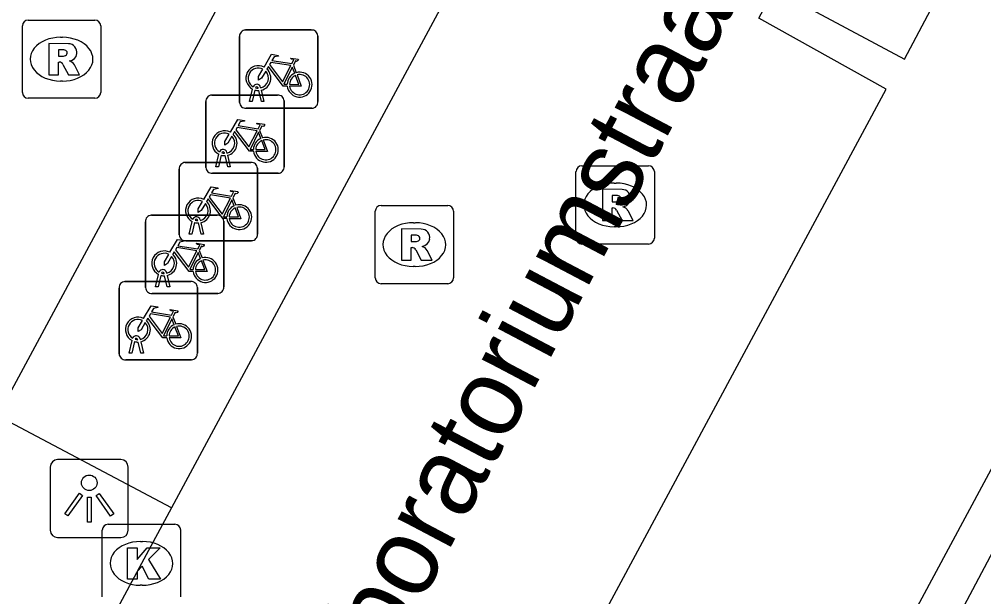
# Model space of a CAD drawing. Extents: x 159489 to 160304, y 383826 to 384530.
# Drawn here: x 159629.86 to 159642.18, y 384196.3 to 384203.68 of the extents above; entities that cross this region are included whole.
import ezdxf

# ---------------------------------------------------------------- set-up
doc = ezdxf.new("R2010")
doc.units = 0
for name, color, linetype in [('IMGEO_Fietsenrek', 7, 'Continuous'), ('IMGEO_Kolk', 7, 'Continuous'), ('IMGEO_Lichtpunt', 7, 'Continuous'), ('IMGEO_Openbare_ruimte_label', 7, 'Continuous'), ('IMGEO_Parkeervlak_open', 7, 'Continuous'), ('IMGEO_Rijbaan_lokaal_gesloten', 7, 'Continuous'), ('IMGEO_Rioolput', 7, 'Continuous'), ('IMGEO_Voetpad_gesloten', 7, 'Continuous'), ('IMGEO_Voetpad_open', 7, 'Continuous')]:
    doc.layers.add(name, color=color, linetype=linetype)

msp = doc.modelspace()

# ---------------------------------------------------------------- linework, layer by layer
at = {"layer": 'IMGEO_Fietsenrek'}
for p, q in [((159632.75, 384203.544), (159633.591, 384203.544)), ((159633.591, 384203.544), (159632.75, 384203.544)), ((159632.675, 384202.619), (159632.675, 384203.46)), ((159632.675, 384203.46), (159632.675, 384202.619)), ((159633.675, 384203.469), (159633.675, 384202.628)), ((159633.675, 384202.628), (159633.675, 384203.469)), ((159633.362, 384203.093), (159633.398, 384202.998)), ((159632.802, 384202.628), (159632.841, 384202.788)), ((159632.871, 384202.776), (159632.836, 384202.628)), ((159632.913, 384202.8), (159632.912, 384202.804)), ((159632.954, 384202.628), (159632.92, 384202.77)), ((159632.944, 384202.811), (159632.945, 384202.804)), ((159632.952, 384202.774), (159632.987, 384202.628)), ((159632.319, 384202.712), (159633.16, 384202.712)), ((159633.16, 384202.712), (159632.319, 384202.712)), ((159632.244, 384201.787), (159632.244, 384202.628)), ((159632.244, 384202.628), (159632.244, 384201.787)), ((159633.6, 384202.544), (159632.759, 384202.544)), ((159632.759, 384202.544), (159633.6, 384202.544)), ((159632.836, 384202.628), (159632.802, 384202.628)), ((159632.987, 384202.628), (159632.954, 384202.628)), ((159633.244, 384202.637), (159633.244, 384201.796)), ((159633.244, 384201.796), (159633.244, 384202.637)), ((159632.931, 384202.261), (159632.967, 384202.166)), ((159632.371, 384201.796), (159632.41, 384201.956)), ((159632.44, 384201.944), (159632.405, 384201.796)), ((159632.482, 384201.968), (159632.481, 384201.972)), ((159632.523, 384201.796), (159632.489, 384201.938)), ((159632.513, 384201.979), (159632.514, 384201.972)), ((159632.521, 384201.942), (159632.556, 384201.796)), ((159631.979, 384201.851), (159632.82, 384201.851)), ((159632.82, 384201.851), (159631.979, 384201.851)), ((159632.405, 384201.796), (159632.371, 384201.796)), ((159632.556, 384201.796), (159632.523, 384201.796)), ((159632.904, 384201.776), (159632.904, 384200.935)), ((159632.904, 384200.935), (159632.904, 384201.776)), ((159631.904, 384200.926), (159631.904, 384201.767)), ((159631.904, 384201.767), (159631.904, 384200.926)), ((159633.169, 384201.712), (159632.328, 384201.712)), ((159632.328, 384201.712), (159633.169, 384201.712)), ((159632.591, 384201.4), (159632.627, 384201.305)), ((159631.548, 384201.176), (159632.389, 384201.176)), ((159632.389, 384201.176), (159631.548, 384201.176)), ((159631.473, 384200.251), (159631.473, 384201.092)), ((159631.473, 384201.092), (159631.473, 384200.251)), ((159632.031, 384200.935), (159632.07, 384201.095)), ((159632.1, 384201.083), (159632.065, 384200.935)), ((159632.142, 384201.107), (159632.141, 384201.111)), ((159632.183, 384200.935), (159632.149, 384201.077)), ((159632.173, 384201.118), (159632.174, 384201.111)), ((159632.181, 384201.081), (159632.216, 384200.935)), ((159632.473, 384201.101), (159632.473, 384200.26)), ((159632.473, 384200.26), (159632.473, 384201.101)), ((159632.065, 384200.935), (159632.031, 384200.935)), ((159632.216, 384200.935), (159632.183, 384200.935)), ((159632.829, 384200.851), (159631.988, 384200.851)), ((159631.988, 384200.851), (159632.829, 384200.851)), ((159632.16, 384200.725), (159632.196, 384200.63)), ((159631.6, 384200.26), (159631.639, 384200.42)), ((159631.711, 384200.432), (159631.71, 384200.436)), ((159631.742, 384200.443), (159631.743, 384200.436)), ((159631.211, 384200.329), (159632.052, 384200.329)), ((159632.052, 384200.329), (159631.211, 384200.329)), ((159631.669, 384200.408), (159631.634, 384200.26)), ((159631.752, 384200.26), (159631.718, 384200.402)), ((159631.75, 384200.406), (159631.785, 384200.26)), ((159631.136, 384199.404), (159631.136, 384200.245)), ((159631.136, 384200.245), (159631.136, 384199.404)), ((159632.398, 384200.176), (159631.557, 384200.176)), ((159631.557, 384200.176), (159632.398, 384200.176)), ((159631.634, 384200.26), (159631.6, 384200.26)), ((159631.785, 384200.26), (159631.752, 384200.26)), ((159632.136, 384200.254), (159632.136, 384199.413)), ((159632.136, 384199.413), (159632.136, 384200.254)), ((159631.823, 384199.878), (159631.859, 384199.783)), ((159631.263, 384199.413), (159631.302, 384199.573)), ((159631.332, 384199.561), (159631.297, 384199.413)), ((159631.374, 384199.585), (159631.373, 384199.589)), ((159631.405, 384199.596), (159631.406, 384199.589)), ((159631.413, 384199.559), (159631.448, 384199.413)), ((159631.415, 384199.413), (159631.381, 384199.555)), ((159632.061, 384199.329), (159631.22, 384199.329)), ((159631.22, 384199.329), (159632.061, 384199.329)), ((159631.297, 384199.413), (159631.263, 384199.413)), ((159631.448, 384199.413), (159631.415, 384199.413))]:
    msp.add_line(p, q, dxfattribs=at)
for points in [[(159632.988, 384203.07), (159633.083, 384203.234), (159633.169, 384203.22), (159633.171, 384203.211), (159633.115, 384203.2), (159633.088, 384203.155), (159633.344, 384203.114)], [(159633.344, 384203.114), (159633.369, 384203.163), (159633.363, 384203.167), (159633.34, 384203.171), (159633.328, 384203.178), (159633.327, 384203.181), (159633.329, 384203.186), (159633.424, 384203.171), (159633.426, 384203.161), (159633.416, 384203.148), (159633.404, 384203.142), (159633.39, 384203.148), (159633.362, 384203.093)], [(159633.009, 384203.018), (159632.957, 384202.928), (159632.917, 384202.903), (159632.918, 384202.95), (159632.973, 384203.044)], [(159633.284, 384202.826), (159633.234, 384202.826), (159633.043, 384203.077), (159633.024, 384203.045)], [(159633.331, 384203.089), (159633.074, 384203.13), (159633.057, 384203.101), (159633.224, 384202.881), (159633.331, 384203.089)], [(159633.379, 384202.991), (159633.349, 384203.068), (159633.24, 384202.85), (159633.283, 384202.85)], [(159633.313, 384202.85), (159633.433, 384202.849), (159633.389, 384202.963)], [(159633.409, 384202.97), (159633.464, 384202.825), (159633.314, 384202.825)], [(159632.557, 384202.238), (159632.652, 384202.402), (159632.738, 384202.388), (159632.74, 384202.379), (159632.684, 384202.368), (159632.657, 384202.323), (159632.913, 384202.282)], [(159632.9, 384202.257), (159632.643, 384202.298), (159632.626, 384202.269), (159632.793, 384202.049), (159632.9, 384202.257)], [(159632.913, 384202.282), (159632.938, 384202.331), (159632.932, 384202.335), (159632.909, 384202.339), (159632.897, 384202.346), (159632.896, 384202.349), (159632.898, 384202.354), (159632.993, 384202.339), (159632.995, 384202.329), (159632.985, 384202.316), (159632.973, 384202.31), (159632.959, 384202.316), (159632.931, 384202.261)], [(159632.578, 384202.186), (159632.526, 384202.096), (159632.486, 384202.071), (159632.487, 384202.118), (159632.542, 384202.212)], [(159632.853, 384201.994), (159632.803, 384201.994), (159632.612, 384202.245), (159632.593, 384202.213)], [(159632.948, 384202.159), (159632.918, 384202.236), (159632.809, 384202.018), (159632.852, 384202.018)], [(159632.882, 384202.018), (159633.002, 384202.017), (159632.958, 384202.131)], [(159632.978, 384202.138), (159633.033, 384201.993), (159632.883, 384201.993)], [(159632.217, 384201.377), (159632.312, 384201.541), (159632.398, 384201.527), (159632.4, 384201.518), (159632.344, 384201.507), (159632.317, 384201.462), (159632.573, 384201.421)], [(159632.56, 384201.396), (159632.303, 384201.437), (159632.286, 384201.408), (159632.453, 384201.188), (159632.56, 384201.396)], [(159632.573, 384201.421), (159632.598, 384201.47), (159632.592, 384201.474), (159632.569, 384201.478), (159632.557, 384201.485), (159632.556, 384201.488), (159632.558, 384201.493), (159632.653, 384201.478), (159632.655, 384201.468), (159632.645, 384201.455), (159632.633, 384201.449), (159632.619, 384201.455), (159632.591, 384201.4)], [(159632.238, 384201.325), (159632.186, 384201.235), (159632.146, 384201.21), (159632.147, 384201.257), (159632.202, 384201.351)], [(159632.513, 384201.133), (159632.463, 384201.133), (159632.272, 384201.384), (159632.253, 384201.352)], [(159632.608, 384201.298), (159632.578, 384201.375), (159632.469, 384201.157), (159632.512, 384201.157)], [(159632.542, 384201.157), (159632.662, 384201.156), (159632.618, 384201.27)], [(159632.638, 384201.277), (159632.693, 384201.132), (159632.543, 384201.132)], [(159631.786, 384200.702), (159631.881, 384200.866), (159631.967, 384200.852), (159631.969, 384200.843), (159631.913, 384200.832), (159631.886, 384200.787), (159632.142, 384200.746)], [(159632.142, 384200.746), (159632.167, 384200.795), (159632.161, 384200.799), (159632.138, 384200.803), (159632.126, 384200.81), (159632.125, 384200.813), (159632.127, 384200.818), (159632.222, 384200.803), (159632.224, 384200.793), (159632.214, 384200.78), (159632.202, 384200.774), (159632.188, 384200.78), (159632.16, 384200.725)], [(159631.807, 384200.65), (159631.755, 384200.56), (159631.715, 384200.535), (159631.716, 384200.582), (159631.771, 384200.676)], [(159632.082, 384200.458), (159632.032, 384200.458), (159631.841, 384200.709), (159631.822, 384200.677)], [(159632.129, 384200.721), (159631.872, 384200.762), (159631.855, 384200.733), (159632.022, 384200.513), (159632.129, 384200.721)], [(159632.177, 384200.623), (159632.147, 384200.7), (159632.038, 384200.482), (159632.081, 384200.482)], [(159632.111, 384200.482), (159632.231, 384200.481), (159632.187, 384200.595)], [(159632.207, 384200.602), (159632.262, 384200.457), (159632.112, 384200.457)], [(159631.449, 384199.855), (159631.544, 384200.019), (159631.63, 384200.005), (159631.632, 384199.996), (159631.576, 384199.985), (159631.549, 384199.94), (159631.805, 384199.899)], [(159631.805, 384199.899), (159631.83, 384199.948), (159631.824, 384199.952), (159631.801, 384199.956), (159631.789, 384199.963), (159631.788, 384199.966), (159631.79, 384199.971), (159631.885, 384199.956), (159631.887, 384199.946), (159631.877, 384199.933), (159631.865, 384199.927), (159631.851, 384199.933), (159631.823, 384199.878)], [(159631.47, 384199.803), (159631.418, 384199.713), (159631.378, 384199.688), (159631.379, 384199.735), (159631.434, 384199.829)], [(159631.745, 384199.611), (159631.695, 384199.611), (159631.504, 384199.862), (159631.485, 384199.83)], [(159631.792, 384199.874), (159631.535, 384199.915), (159631.518, 384199.886), (159631.685, 384199.666), (159631.792, 384199.874)], [(159631.84, 384199.776), (159631.81, 384199.853), (159631.701, 384199.635), (159631.744, 384199.635)], [(159631.774, 384199.635), (159631.894, 384199.634), (159631.85, 384199.748)], [(159631.87, 384199.755), (159631.925, 384199.61), (159631.775, 384199.61)]]:
    msp.add_lwpolyline(points, dxfattribs=at)
for centre, radius, start, end in [((159632.753, 384203.466), 0.0779, 92.4484, 184.2845), ((159632.753, 384203.466), 0.0779, 92.4484, 184.2845), ((159633.597, 384203.466), 0.0779, 2.4484, 94.2845), ((159633.597, 384203.466), 0.0779, 2.4484, 94.2845), ((159632.915, 384202.929), 0.159, 62.6766, 242.1369), ((159632.915, 384202.929), 0.129, 63.3192, 238.903), ((159632.915, 384202.929), 0.129, 283.6043, 43.4302), ((159632.915, 384202.929), 0.159, 283.5766, 46.6042), ((159633.442, 384202.845), 0.159, 113.3408, 178.3217), ((159633.442, 384202.845), 0.159, 187.0065, 105.7708), ((159633.442, 384202.845), 0.129, 113.923, 177.9556), ((159633.442, 384202.845), 0.129, 188.6715, 104.5883), ((159632.895, 384202.8), 0.0499, 12.8025, 158.6934), ((159632.915, 384202.929), 0.159, 253.9967, 271.7867), ((159632.895, 384202.8), 0.0174, 12.8025, 163.4502), ((159632.915, 384202.929), 0.129, 253.415, 269.0204), ((159632.322, 384202.634), 0.0779, 92.4484, 184.2845), ((159632.322, 384202.634), 0.0779, 92.4484, 184.2845), ((159633.166, 384202.634), 0.0779, 2.4484, 94.2845), ((159633.166, 384202.634), 0.0779, 2.4484, 94.2845), ((159632.753, 384202.622), 0.0779, 182.4484, 274.2845), ((159632.753, 384202.622), 0.0779, 182.4484, 274.2845), ((159633.597, 384202.622), 0.0779, 272.4484, 4.2845), ((159633.597, 384202.622), 0.0779, 272.4484, 4.2845), ((159632.484, 384202.097), 0.159, 62.6766, 242.1369), ((159632.484, 384202.097), 0.129, 63.3192, 238.903), ((159632.484, 384202.097), 0.129, 283.6043, 43.4302), ((159632.484, 384202.097), 0.159, 283.5766, 46.6042), ((159633.011, 384202.013), 0.159, 113.3408, 178.3217), ((159633.011, 384202.013), 0.159, 187.0065, 105.7708), ((159633.011, 384202.013), 0.129, 113.923, 177.9556), ((159633.011, 384202.013), 0.129, 188.6715, 104.5883), ((159632.464, 384201.968), 0.0499, 12.8025, 158.6934), ((159632.484, 384202.097), 0.159, 253.9967, 271.7867), ((159632.464, 384201.968), 0.0174, 12.8025, 163.4502), ((159632.484, 384202.097), 0.129, 253.415, 269.0204), ((159631.982, 384201.773), 0.0779, 92.4484, 184.2845), ((159631.982, 384201.773), 0.0779, 92.4484, 184.2845), ((159632.322, 384201.79), 0.0779, 182.4484, 274.2845), ((159632.322, 384201.79), 0.0779, 182.4484, 274.2845), ((159632.826, 384201.773), 0.0779, 2.4484, 94.2845), ((159632.826, 384201.773), 0.0779, 2.4484, 94.2845), ((159633.166, 384201.79), 0.0779, 272.4484, 4.2845), ((159633.166, 384201.79), 0.0779, 272.4484, 4.2845), ((159632.144, 384201.236), 0.159, 62.6766, 242.1369), ((159632.144, 384201.236), 0.129, 63.3192, 238.903), ((159632.144, 384201.236), 0.129, 283.6043, 43.4302), ((159632.144, 384201.236), 0.159, 283.5766, 46.6042), ((159632.671, 384201.152), 0.159, 113.3408, 178.3217), ((159632.671, 384201.152), 0.159, 187.0065, 105.7708), ((159631.551, 384201.098), 0.0779, 92.4484, 184.2845), ((159631.551, 384201.098), 0.0779, 92.4484, 184.2845), ((159632.395, 384201.098), 0.0779, 2.4484, 94.2845), ((159632.395, 384201.098), 0.0779, 2.4484, 94.2845), ((159632.671, 384201.152), 0.129, 113.923, 177.9556), ((159632.671, 384201.152), 0.129, 188.6715, 104.5883), ((159632.124, 384201.107), 0.0499, 12.8025, 158.6934), ((159632.144, 384201.236), 0.159, 253.9967, 271.7867), ((159632.124, 384201.107), 0.0174, 12.8025, 163.4502), ((159632.144, 384201.236), 0.129, 253.415, 269.0204), ((159631.982, 384200.929), 0.0779, 182.4484, 274.2845), ((159631.982, 384200.929), 0.0779, 182.4484, 274.2845), ((159632.826, 384200.929), 0.0779, 272.4484, 4.2845), ((159632.826, 384200.929), 0.0779, 272.4484, 4.2845), ((159631.713, 384200.561), 0.159, 62.6766, 242.1369), ((159631.713, 384200.561), 0.129, 63.3192, 238.903), ((159631.713, 384200.561), 0.159, 283.5766, 46.6042), ((159631.713, 384200.561), 0.129, 283.6043, 43.4302), ((159632.24, 384200.477), 0.159, 113.3408, 178.3217), ((159632.24, 384200.477), 0.159, 187.0065, 105.7708), ((159632.24, 384200.477), 0.129, 113.923, 177.9556), ((159632.24, 384200.477), 0.129, 188.6715, 104.5883), ((159631.693, 384200.432), 0.0499, 12.8025, 158.6934), ((159631.693, 384200.432), 0.0174, 12.8025, 163.4502), ((159631.713, 384200.561), 0.129, 253.415, 269.0204), ((159631.214, 384200.251), 0.0779, 92.4484, 184.2845), ((159631.214, 384200.251), 0.0779, 92.4484, 184.2845), ((159631.713, 384200.561), 0.159, 253.9967, 271.7867), ((159632.058, 384200.251), 0.0779, 2.4484, 94.2845), ((159632.058, 384200.251), 0.0779, 2.4484, 94.2845), ((159631.551, 384200.254), 0.0779, 182.4484, 274.2845), ((159631.551, 384200.254), 0.0779, 182.4484, 274.2845), ((159632.395, 384200.254), 0.0779, 272.4484, 4.2845), ((159632.395, 384200.254), 0.0779, 272.4484, 4.2845), ((159631.376, 384199.714), 0.159, 62.6766, 242.1369), ((159631.376, 384199.714), 0.129, 63.3192, 238.903), ((159631.376, 384199.714), 0.159, 283.5766, 46.6042), ((159631.376, 384199.714), 0.129, 283.6043, 43.4302), ((159631.903, 384199.63), 0.159, 113.3408, 178.3217), ((159631.903, 384199.63), 0.159, 187.0065, 105.7708), ((159631.903, 384199.63), 0.129, 113.923, 177.9556), ((159631.903, 384199.63), 0.129, 188.6715, 104.5883), ((159631.356, 384199.585), 0.0499, 12.8025, 158.6934), ((159631.376, 384199.714), 0.159, 253.9967, 271.7867), ((159631.356, 384199.585), 0.0174, 12.8025, 163.4502), ((159631.376, 384199.714), 0.129, 253.415, 269.0204), ((159631.214, 384199.407), 0.0779, 182.4484, 274.2845), ((159631.214, 384199.407), 0.0779, 182.4484, 274.2845), ((159632.058, 384199.407), 0.0779, 272.4484, 4.2845), ((159632.058, 384199.407), 0.0779, 272.4484, 4.2845)]:
    msp.add_arc(centre, radius, start, end, dxfattribs=at)
at = {"layer": 'IMGEO_Kolk'}
for p, q in [((159630.996, 384197.226), (159631.848, 384197.226)), ((159630.921, 384196.3), (159630.921, 384197.152)), ((159631.922, 384197.152), (159631.922, 384196.3)), ((159631.409, 384197.006), (159631.434, 384197.006)), ((159631.432, 384196.446), (159631.407, 384196.446))]:
    msp.add_line(p, q, dxfattribs=at)
for points in [[(159630.996, 384197.226), (159631.848, 384197.226)], [(159630.921, 384196.3), (159630.921, 384197.152)], [(159631.922, 384197.152), (159631.922, 384196.3)], [(159631.242, 384196.926), (159631.365, 384196.926), (159631.365, 384196.775), (159631.495, 384196.926), (159631.659, 384196.926), (159631.513, 384196.775), (159631.666, 384196.526), (159631.514, 384196.526), (159631.429, 384196.69), (159631.365, 384196.623), (159631.365, 384196.526), (159631.242, 384196.526), (159631.242, 384196.926)]]:
    msp.add_lwpolyline(points, dxfattribs=at)
for centre, start, end in [((159630.998, 384197.15), 91.552, 178.448), ((159630.998, 384197.15), 91.552, 178.448), ((159631.846, 384197.15), 1.552, 88.448), ((159631.846, 384197.15), 1.552, 88.448)]:
    msp.add_arc(centre, 0.0765, start, end, dxfattribs=at)
for centre, major_axis, ratio, start_param, end_param in [((159631.408, 384196.726), (-0.387, 0.002), 0.722429, 4.712389, 7.853982), ((159631.433, 384196.726), (-0.39, 0.002), 0.717154, 1.570796, 4.712389)]:
    msp.add_ellipse(centre, major_axis=major_axis, ratio=ratio, start_param=start_param, end_param=end_param, dxfattribs=at)
at = {"layer": 'IMGEO_Lichtpunt'}
for p, q in [((159630.256, 384197.958), (159630.256, 384197.151)), ((159630.256, 384197.958), (159630.256, 384197.151)), ((159631.158, 384198.053), (159630.35, 384198.053)), ((159631.158, 384198.053), (159630.35, 384198.053)), ((159631.252, 384197.151), (159631.252, 384197.958)), ((159631.252, 384197.151), (159631.252, 384197.958)), ((159630.35, 384197.057), (159631.158, 384197.057)), ((159630.35, 384197.057), (159631.158, 384197.057))]:
    msp.add_line(p, q, dxfattribs=at)
for points in [[(159630.63, 384197.622), (159630.669, 384197.594), (159630.481, 384197.332), (159630.443, 384197.359), (159630.63, 384197.622)], [(159630.842, 384197.594), (159630.88, 384197.621), (159631.067, 384197.359), (159631.028, 384197.331), (159630.842, 384197.594)], [(159630.732, 384197.574), (159630.779, 384197.574), (159630.779, 384197.252), (159630.732, 384197.252), (159630.732, 384197.574)]]:
    msp.add_lwpolyline(points, dxfattribs=at)
msp.add_circle((159630.755, 384197.756), 0.0994, dxfattribs=at)
for centre, start, end in [((159630.35, 384197.958), 90, 180), ((159630.35, 384197.958), 90, 180), ((159631.158, 384197.958), 0, 90), ((159631.158, 384197.958), 0, 90), ((159630.35, 384197.151), 180, 270), ((159630.35, 384197.151), 180, 270), ((159631.158, 384197.151), 270, 0), ((159631.158, 384197.151), 270, 360)]:
    msp.add_arc(centre, 0.0946, start, end, dxfattribs=at)
at = {"layer": 'IMGEO_Parkeervlak_open'}
msp.add_lwpolyline([(159638.592, 384189.885), (159647.537, 384206.76), (159652.006, 384204.401)], dxfattribs=at)
at = {"layer": 'IMGEO_Rijbaan_lokaal_gesloten'}
for points in [[(159621.259, 384166.179), (159621.791, 384167.209), (159629.16, 384180.893), (159636.525, 384194.583), (159640.934, 384202.788), (159639.307, 384203.695), (159640.5, 384205.922), (159642.138, 384205.059), (159643.404, 384207.416), (159644.131, 384208.747)], [(159635.354, 384204.03), (159631.805, 384197.437)], [(159631.805, 384197.437), (159631.422, 384196.726), (159624.053, 384183.005), (159617.514, 384170.805)]]:
    msp.add_lwpolyline(points, dxfattribs=at)
at = {"layer": 'IMGEO_Rioolput'}
for p, q in [((159629.975, 384203.671), (159630.827, 384203.671)), ((159629.9, 384202.745), (159629.9, 384203.597)), ((159630.901, 384203.597), (159630.901, 384202.745)), ((159630.388, 384203.451), (159630.413, 384203.451)), ((159630.411, 384202.891), (159630.386, 384202.891)), ((159630.827, 384202.671), (159629.975, 384202.671)), ((159637.048, 384201.808), (159637.9, 384201.808)), ((159636.973, 384200.882), (159636.973, 384201.734)), ((159637.974, 384201.734), (159637.974, 384200.882)), ((159637.461, 384201.588), (159637.486, 384201.588)), ((159634.482, 384201.301), (159635.334, 384201.301)), ((159634.407, 384200.375), (159634.407, 384201.227)), ((159635.408, 384201.227), (159635.408, 384200.375)), ((159634.895, 384201.081), (159634.92, 384201.081)), ((159637.484, 384201.028), (159637.459, 384201.028)), ((159637.9, 384200.808), (159637.048, 384200.808)), ((159634.918, 384200.521), (159634.893, 384200.521)), ((159635.334, 384200.301), (159634.482, 384200.301))]:
    msp.add_line(p, q, dxfattribs=at)
for points in [[(159629.975, 384203.671), (159630.827, 384203.671)], [(159629.9, 384202.745), (159629.9, 384203.597)], [(159630.901, 384203.597), (159630.901, 384202.745)], [(159630.489, 384203.369), (159630.237, 384203.371), (159630.237, 384202.971)], [(159630.415, 384203.29), (159630.361, 384203.29), (159630.361, 384203.209)], [(159630.237, 384202.971), (159630.361, 384202.971), (159630.361, 384203.133), (159630.372, 384203.133)], [(159630.361, 384203.209), (159630.413, 384203.209)], [(159630.419, 384203.104), (159630.49, 384202.971), (159630.63, 384202.971), (159630.565, 384203.097)], [(159630.827, 384202.671), (159629.975, 384202.671)], [(159637.048, 384201.808), (159637.9, 384201.808)], [(159636.973, 384200.882), (159636.973, 384201.734)], [(159637.974, 384201.734), (159637.974, 384200.882)], [(159637.562, 384201.506), (159637.31, 384201.508), (159637.31, 384201.108)], [(159637.488, 384201.427), (159637.434, 384201.427), (159637.434, 384201.346)], [(159634.482, 384201.301), (159635.334, 384201.301)], [(159637.434, 384201.346), (159637.486, 384201.346)], [(159634.407, 384200.375), (159634.407, 384201.227)], [(159635.408, 384201.227), (159635.408, 384200.375)], [(159637.31, 384201.108), (159637.434, 384201.108), (159637.434, 384201.27), (159637.445, 384201.27)], [(159637.492, 384201.241), (159637.563, 384201.108), (159637.703, 384201.108), (159637.638, 384201.234)], [(159634.996, 384200.999), (159634.744, 384201.001), (159634.744, 384200.601)], [(159634.922, 384200.92), (159634.868, 384200.92), (159634.868, 384200.839)], [(159634.868, 384200.839), (159634.92, 384200.839)], [(159637.9, 384200.808), (159637.048, 384200.808)], [(159634.744, 384200.601), (159634.868, 384200.601), (159634.868, 384200.763), (159634.879, 384200.763)], [(159634.926, 384200.734), (159634.997, 384200.601), (159635.137, 384200.601), (159635.072, 384200.727)], [(159635.334, 384200.301), (159634.482, 384200.301)]]:
    msp.add_lwpolyline(points, dxfattribs=at)
for centre, radius, start, end in [((159629.977, 384203.595), 0.0765, 91.552, 178.448), ((159629.977, 384203.595), 0.0765, 91.552, 178.448), ((159630.825, 384203.595), 0.0765, 1.552, 88.448), ((159630.825, 384203.595), 0.0765, 1.552, 88.448), ((159630.421, 384203.194), 0.0964, 77.0061, 93.1865), ((159630.435, 384203.251), 0.0378, 276.6634, 79.6772), ((159630.488, 384203.259), 0.109, 350.3612, 89.416), ((159630.371, 384203.08), 0.0533, 26.0293, 88.6989), ((159630.397, 384203.398), 0.19, 274.7715, 282.9687), ((159630.486, 384203.259), 0.112, 277.5842, 350.9817), ((159630.47, 384203.044), 0.108, 29.5134, 73.7905), ((159629.977, 384202.747), 0.0765, 181.552, 268.448), ((159629.977, 384202.747), 0.0765, 181.552, 268.448), ((159630.825, 384202.747), 0.0765, 271.552, 358.448), ((159630.825, 384202.747), 0.0765, 271.552, 358.448), ((159637.05, 384201.732), 0.0765, 91.552, 178.448), ((159637.05, 384201.732), 0.0765, 91.552, 178.448), ((159637.898, 384201.732), 0.0765, 1.552, 88.448), ((159637.898, 384201.732), 0.0765, 1.552, 88.448), ((159637.494, 384201.331), 0.0964, 77.0061, 93.1865), ((159637.508, 384201.388), 0.0378, 276.6634, 79.6772), ((159637.561, 384201.396), 0.109, 350.3612, 89.416), ((159634.484, 384201.225), 0.0765, 91.552, 178.448), ((159634.484, 384201.225), 0.0765, 91.552, 178.448), ((159635.332, 384201.225), 0.0765, 1.552, 88.448), ((159635.332, 384201.225), 0.0765, 1.552, 88.448), ((159637.47, 384201.535), 0.19, 274.7715, 282.9687), ((159637.559, 384201.396), 0.112, 277.5842, 350.9817), ((159637.543, 384201.181), 0.108, 29.5134, 73.7905), ((159637.444, 384201.217), 0.0533, 26.0293, 88.6989), ((159634.928, 384200.824), 0.0964, 77.0061, 93.1865), ((159634.942, 384200.881), 0.0378, 276.6634, 79.6772), ((159634.995, 384200.889), 0.109, 350.3612, 89.416), ((159634.904, 384201.028), 0.19, 274.7715, 282.9687), ((159634.993, 384200.889), 0.112, 277.5842, 350.9817), ((159637.05, 384200.884), 0.0765, 181.552, 268.448), ((159637.05, 384200.884), 0.0765, 181.552, 268.448), ((159637.898, 384200.884), 0.0765, 271.552, 358.448), ((159637.898, 384200.884), 0.0765, 271.552, 358.448), ((159634.878, 384200.71), 0.0533, 26.0293, 88.6989), ((159634.977, 384200.674), 0.108, 29.5134, 73.7905), ((159634.484, 384200.377), 0.0765, 181.552, 268.448), ((159634.484, 384200.377), 0.0765, 181.552, 268.448), ((159635.332, 384200.377), 0.0765, 271.552, 358.448), ((159635.332, 384200.377), 0.0765, 271.552, 358.448)]:
    msp.add_arc(centre, radius, start, end, dxfattribs=at)
for centre, major_axis, ratio, start_param, end_param in [((159630.387, 384203.171), (-0.387, 0.002), 0.722429, 4.712389, 7.853982), ((159630.412, 384203.171), (-0.39, 0.002), 0.717154, 1.570796, 4.712389), ((159637.46, 384201.308), (-0.387, 0.002), 0.722429, 4.712389, 7.853982), ((159637.485, 384201.308), (-0.39, 0.002), 0.717154, 1.570796, 4.712389), ((159634.894, 384200.801), (-0.387, 0.002), 0.722429, 4.712389, 7.853982), ((159634.919, 384200.801), (-0.39, 0.002), 0.717154, 1.570796, 4.712389)]:
    msp.add_ellipse(centre, major_axis=major_axis, ratio=ratio, start_param=start_param, end_param=end_param, dxfattribs=at)
at = {"layer": 'IMGEO_Voetpad_gesloten'}
msp.add_lwpolyline([(159641.952, 384204.655), (159640.492, 384205.437), (159639.672, 384203.978), (159641.17, 384203.172), (159641.952, 384204.655)], dxfattribs=at)
at = {"layer": 'IMGEO_Voetpad_open'}
for points in [[(159647.326, 384207.335), (159624.039, 384163.992)], [(159629.581, 384198.613), (159633.141, 384205.225)], [(159631.805, 384197.437), (159629.581, 384198.613)]]:
    msp.add_lwpolyline(points, dxfattribs=at)

# ---------------------------------------------------------------- texts
at = {"layer": 'IMGEO_Openbare_ruimte_label'}
msp.add_text('Laboratoriumstraat', height=1, rotation=62.2041, dxfattribs=at).set_placement((159633.945, 384194.224))

doc.saveas('drawing.dxf')
